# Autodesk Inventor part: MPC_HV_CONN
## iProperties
Shininess: 64.0
Length Units: 11272
Angle Units: 11279
Time Units: 11290
Mass Units: 11286
Length Display Precision: 3
Angle Display Precision: 2
Compacted: True
Part Number: MPC_HV_CONN
Document SubType Name: Modeling
Created: 2004-08
Designer: John Blackburn
Manufacturer: Standard
Standards Organization: Custom
Material: Aluminum-6061-AHC
Density: 0.0
Volumn: 0.0
Area: 0.0
PropertySet Name: Model Information
Control State: 0
Master: False
Checked Out: False
Author: John Blackburn
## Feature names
1. Base1
